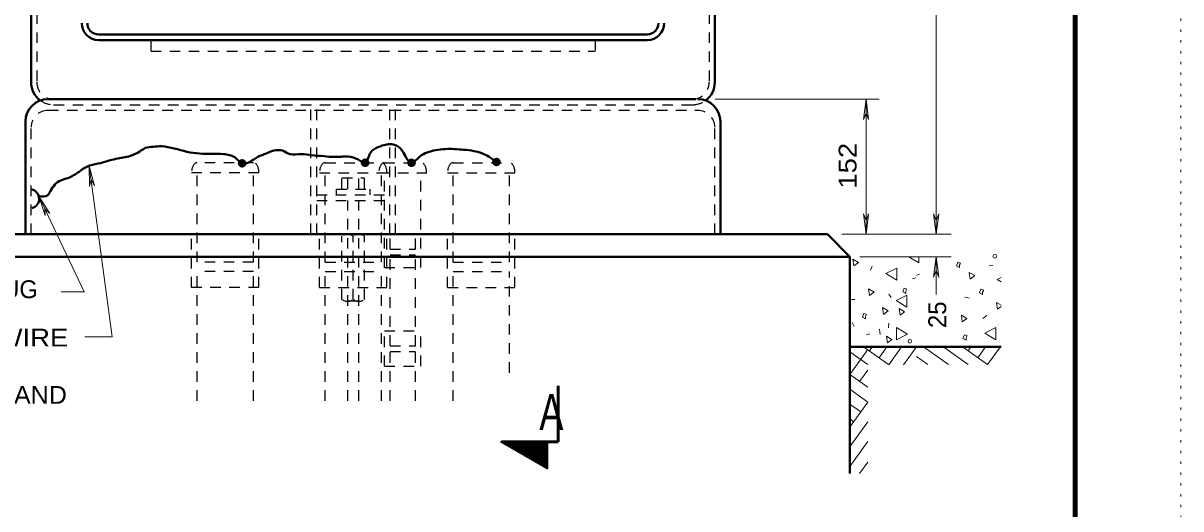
# Model space of a CAD drawing. Extents: x 312583 to 312854, y 144419 to 144597.
# Drawn here: x 312804.21 to 312853.5, y 144509.14 to 144529.81 of the extents above; entities that cross this region are included whole.
import ezdxf
from ezdxf.enums import TextEntityAlignment as Align

# ---------------------------------------------------------------- set-up
doc = ezdxf.new("R2010")
doc.units = 0
doc.header["$LTSCALE"] = 0.3
doc.linetypes.add('DOTTED', pattern=[1.5, 0.3, -1.2])
doc.linetypes.add('SHORT_DASHED', pattern=[2.7, 1.5, -1.2])
doc.layers.add('1', color=7, linetype='Continuous', lineweight=25)
doc.layers.add('2', color=7, linetype='Continuous', lineweight=13)

msp = doc.modelspace()

# ---------------------------------------------------------------- linework, layer by layer
at = {"layer": '1', "lineweight": 158}
msp.add_line((312849, 144423.1446), (312849, 144585.0846), dxfattribs=at)
at = {"layer": '1', "lineweight": 40}
for p, q in [((312804.5487, 144565.8673), (312804.5487, 144527.2963)), ((312833.659, 144565.8673), (312833.659, 144527.2963)), ((312807.4237, 144529.328), (312830.784, 144529.328)), ((312807.4237, 144529.0903), (312830.784, 144529.0903)), ((312805.2693, 144526.5756), (312832.8463, 144526.5756)), ((312804.311, 144520.8256), (312804.311, 144525.6173)), ((312833.8967, 144520.8256), (312833.8967, 144525.6173)), ((312838.4507, 144520.8256), (312839.409, 144519.8673)), ((312839.409, 144510.6366), (312839.409, 144519.8673)), ((312839.409, 144516.034), (312845.849, 144516.034))]:
    msp.add_line(p, q, dxfattribs=at)
at = {"layer": '1', "linetype": 'SHORT_DASHED'}
for p, q in [((312804.7863, 144565.8673), (312804.7863, 144527.2963)), ((312833.4213, 144565.8673), (312833.4213, 144527.2963)), ((312809.6393, 144529.0903), (312809.6393, 144528.615)), ((312828.5683, 144529.0903), (312828.5683, 144528.615)), ((312809.6393, 144528.615), (312828.5683, 144528.615)), ((312805.507, 144526.5756), (312832.7007, 144526.5756)), ((312805.507, 144526.338), (312832.7007, 144526.338)), ((312816.4627, 144520.8256), (312816.4627, 144526.338)), ((312816.708, 144520.8256), (312816.708, 144526.338)), ((312819.8207, 144520.8256), (312819.8207, 144526.338)), ((312820.0583, 144520.8256), (312820.0583, 144526.338)), ((312805.2693, 144526.1003), (312832.9383, 144526.1003)), ((312804.5487, 144520.8256), (312804.5487, 144525.3796)), ((312833.659, 144520.8256), (312833.659, 144525.3796)), ((312814.0093, 144523.8693), (312811.6173, 144523.8693)), ((312817.0683, 144523.8693), (312819.4603, 144523.8693)), ((312819.5907, 144523.8693), (312821.147, 144523.8693)), ((312822.5117, 144523.8693), (312824.9113, 144523.8693)), ((312814.247, 144523.4323), (312811.372, 144523.4323)), ((312811.6173, 144519.6373), (312811.6173, 144523.4323)), ((312814.0093, 144519.6373), (312814.0093, 144523.4323)), ((312816.823, 144523.4323), (312819.698, 144523.4323)), ((312817.0683, 144519.6373), (312817.0683, 144523.4323)), ((312819.353, 144523.4323), (312821.3923, 144523.4323)), ((312819.4603, 144519.6373), (312819.4603, 144523.4323)), ((312819.5907, 144519.4073), (312819.5907, 144523.4323)), ((312821.147, 144519.4073), (312821.147, 144523.4323)), ((312822.274, 144523.4323), (312825.149, 144523.4323)), ((312822.5117, 144519.6373), (312822.5117, 144523.4323)), ((312824.9113, 144519.6373), (312824.9113, 144523.4323)), ((312818.0267, 144522.7423), (312818.0267, 144523.2253)), ((312818.502, 144522.7423), (312818.502, 144523.2253)), ((312818.7397, 144522.7423), (312818.7397, 144523.2253)), ((312816.708, 144522.5046), (312819.8207, 144522.5046)), ((312817.5437, 144522.7423), (312818.985, 144522.7423)), ((312817.5437, 144522.5046), (312817.5437, 144522.7423)), ((312818.985, 144522.5046), (312818.985, 144522.7423)), ((312816.708, 144522.267), (312819.8207, 144522.267)), ((312818.0267, 144513.734), (312818.0267, 144522.267)), ((312818.502, 144513.734), (312818.502, 144522.267)), ((312811.372, 144518.5563), (312811.372, 144520.8256)), ((312814.247, 144518.5563), (312814.247, 144520.8256)), ((312816.823, 144518.5563), (312816.823, 144520.8256)), ((312819.698, 144518.5563), (312819.698, 144520.8256)), ((312819.8283, 144520.1893), (312819.8283, 144520.8256)), ((312820.9093, 144520.1893), (312820.9093, 144520.8256)), ((312822.274, 144518.5563), (312822.274, 144520.8256)), ((312825.149, 144518.5563), (312825.149, 144520.8256)), ((312817.7813, 144518.0503), (312817.7813, 144520.7413)), ((312818.2643, 144518.0503), (312818.2643, 144520.7413)), ((312818.7397, 144518.0503), (312818.7397, 144520.7413)), ((312819.8283, 144520.1893), (312820.9093, 144520.1893)), ((312819.8283, 144519.944), (312820.9093, 144519.944)), ((312819.8283, 144516.0723), (312819.8283, 144519.944)), ((312820.9093, 144516.0723), (312820.9093, 144519.944)), ((312814.0093, 144519.6373), (312811.6173, 144519.6373)), ((312817.0683, 144519.6373), (312819.4603, 144519.6373)), ((312819.5907, 144519.4073), (312821.147, 144519.4073)), ((312822.5117, 144519.6373), (312824.9113, 144519.6373)), ((312814.0093, 144519.2386), (312811.6173, 144519.2386)), ((312811.6173, 144513.734), (312811.6173, 144519.2386)), ((312814.0093, 144513.734), (312814.0093, 144519.2386)), ((312817.0683, 144519.2386), (312819.4603, 144519.2386)), ((312817.0683, 144513.734), (312817.0683, 144519.2386)), ((312819.4603, 144513.734), (312819.4603, 144519.2386)), ((312822.5117, 144519.2386), (312824.9113, 144519.2386)), ((312822.5117, 144513.734), (312822.5117, 144519.2386)), ((312824.9113, 144514.93), (312824.9113, 144519.2386)), ((312814.247, 144518.5563), (312811.372, 144518.5563)), ((312816.823, 144518.5563), (312819.698, 144518.5563)), ((312822.274, 144518.5563), (312825.149, 144518.5563)), ((312818.502, 144517.9736), (312818.0267, 144517.9736)), ((312819.5907, 144515.206), (312819.5907, 144516.7163)), ((312819.5907, 144516.7163), (312821.147, 144516.7163)), ((312821.147, 144515.206), (312821.147, 144516.7163)), ((312819.8283, 144516.0723), (312820.9093, 144516.0723)), ((312819.8283, 144515.827), (312820.9093, 144515.827)), ((312819.8283, 144513.734), (312819.8283, 144515.827)), ((312820.9093, 144513.734), (312820.9093, 144515.827)), ((312819.5907, 144515.206), (312821.147, 144515.206))]:
    msp.add_line(p, q, dxfattribs=at)
at = {"layer": '1', "lineweight": 53}
for p in [(312826.9813, 144514.378), (312826.506, 144511.986)]:
    msp.add_line(p, (312826.9813, 144511.986), dxfattribs=at)
at = {"layer": '1', "lineweight": 35}
for p, q in [((312824.6047, 144511.986), (312824.6047, 144511.9706)), ((312824.6353, 144511.986), (312824.6277, 144511.963)), ((312824.666, 144511.986), (312824.643, 144511.9476)), ((312824.689, 144511.986), (312824.666, 144511.94)), ((312824.7197, 144511.986), (312824.689, 144511.9246)), ((312824.7427, 144511.986), (312824.7043, 144511.917)), ((312824.7733, 144511.986), (312824.7273, 144511.9016)), ((312824.804, 144511.986), (312824.7503, 144511.894)), ((312824.8347, 144511.986), (312824.7657, 144511.8786)), ((312824.8577, 144511.986), (312824.7887, 144511.871)), ((312824.8807, 144511.986), (312824.8117, 144511.8556)), ((312824.9113, 144511.986), (312824.8347, 144511.848)), ((312824.9343, 144511.986), (312824.85, 144511.8326)), ((312824.965, 144511.986), (312824.873, 144511.8173)), ((312824.9957, 144511.986), (312824.896, 144511.8096)), ((312825.0263, 144511.986), (312824.9113, 144511.7943)), ((312825.0493, 144511.986), (312824.9343, 144511.779)), ((312825.08, 144511.986), (312824.9573, 144511.7713)), ((312825.103, 144511.986), (312824.9727, 144511.756)), ((312825.1337, 144511.986), (312824.9957, 144511.7483)), ((312825.1643, 144511.986), (312825.0187, 144511.733)), ((312825.1873, 144511.986), (312825.034, 144511.7253)), ((312825.218, 144511.986), (312825.0647, 144511.71)), ((312825.241, 144511.986), (312825.08, 144511.7023)), ((312825.2717, 144511.986), (312825.103, 144511.687)), ((312825.3023, 144511.986), (312825.126, 144511.6793)), ((312825.3253, 144511.986), (312825.1413, 144511.664)), ((312825.356, 144511.986), (312825.1643, 144511.6563)), ((312825.379, 144511.986), (312825.1873, 144511.641)), ((312825.4097, 144511.986), (312825.2027, 144511.6256)), ((312825.4327, 144511.986), (312825.2257, 144511.618)), ((312825.4633, 144511.986), (312825.2487, 144511.6026)), ((312825.494, 144511.986), (312825.264, 144511.5873)), ((312825.5247, 144511.986), (312825.287, 144511.5796)), ((312825.5477, 144511.986), (312825.31, 144511.5643)), ((312825.5707, 144511.986), (312825.333, 144511.5566)), ((312825.6013, 144511.986), (312825.3483, 144511.5413)), ((312825.632, 144511.986), (312825.3713, 144511.5336)), ((312825.655, 144511.986), (312825.3943, 144511.5183)), ((312825.6857, 144511.986), (312825.4097, 144511.5106)), ((312825.7163, 144511.986), (312825.4327, 144511.4953)), ((312825.7393, 144511.986), (312825.4557, 144511.4876)), ((312825.77, 144511.986), (312825.471, 144511.4723)), ((312825.8007, 144511.986), (312825.494, 144511.4646)), ((312825.8237, 144511.986), (312825.517, 144511.4493)), ((312825.8543, 144511.9783), (312825.5323, 144511.434)), ((312825.8773, 144511.986), (312825.563, 144511.4263)), ((312825.908, 144511.986), (312825.5783, 144511.411)), ((312825.931, 144511.986), (312825.6013, 144511.4033)), ((312825.9617, 144511.986), (312825.6243, 144511.388)), ((312825.9923, 144511.986), (312825.6397, 144511.3803)), ((312826.023, 144511.986), (312825.6627, 144511.365)), ((312826.046, 144511.986), (312825.6857, 144511.3573)), ((312826.069, 144511.986), (312825.701, 144511.342)), ((312826.0997, 144511.9783), (312825.724, 144511.3343)), ((312826.1303, 144511.986), (312825.747, 144511.319)), ((312826.1533, 144511.986), (312825.7623, 144511.3113)), ((312826.184, 144511.986), (312825.7853, 144511.296)), ((312826.2147, 144511.986), (312825.8083, 144511.2806)), ((312826.2377, 144511.986), (312825.8313, 144511.273)), ((312826.2683, 144511.986), (312825.8467, 144511.2576)), ((312826.299, 144511.986), (312825.8697, 144511.2423)), ((312826.322, 144511.9783), (312825.8927, 144511.2346)), ((312826.3527, 144511.9783), (312825.908, 144511.2193)), ((312826.3757, 144511.986), (312825.931, 144511.2116)), ((312826.4063, 144511.986), (312825.954, 144511.1963)), ((312826.4293, 144511.986), (312825.9693, 144511.1886)), ((312826.46, 144511.986), (312825.9923, 144511.1733)), ((312826.4907, 144511.986), (312826.0153, 144511.1656)), ((312826.506, 144511.963), (312826.0307, 144511.1503)), ((312826.506, 144511.9093), (312826.0613, 144511.1426)), ((312826.506, 144511.871), (312826.0767, 144511.1273)), ((312826.506, 144511.8173), (312826.0997, 144511.1196)), ((312826.506, 144511.7713), (312826.1227, 144511.1043)), ((312826.506, 144511.7253), (312826.138, 144511.089)), ((312826.506, 144511.6793), (312826.161, 144511.0813)), ((312826.506, 144511.6256), (312826.184, 144511.066)), ((312826.506, 144511.5796), (312826.1993, 144511.0506)), ((312826.506, 144511.5336), (312826.2223, 144511.043)), ((312826.506, 144511.48), (312826.2377, 144511.0276)), ((312826.506, 144511.434), (312826.2607, 144511.02)), ((312826.506, 144511.388), (312826.2837, 144511.0046)), ((312826.506, 144511.3343), (312826.299, 144510.997)), ((312826.506, 144511.2883), (312826.3297, 144510.9816)), ((312826.506, 144511.2423), (312826.345, 144510.974)), ((312826.506, 144511.1963), (312826.368, 144510.9586)), ((312826.506, 144511.1426), (312826.391, 144510.951)), ((312826.506, 144511.1043), (312826.4063, 144510.9356)), ((312826.506, 144511.0506), (312826.4293, 144510.928)), ((312826.506, 144511.0046), (312826.4523, 144510.9126)), ((312826.506, 144510.951), (312826.4677, 144510.8973)), ((312826.506, 144510.905), (312826.4907, 144510.8896))]:
    msp.add_line(p, q, dxfattribs=at)
at = {"layer": '1', "linetype": 'DOTTED', "lineweight": 13}
msp.add_lwpolyline([(312601.2, 144418.5846), (312853.5, 144418.5846), (312853.5, 144596.7846)], dxfattribs=at)
at = {"layer": '1', "linetype": 'SHORT_DASHED'}
msp.add_lwpolyline([(312817.7813, 144522.7423), (312817.7813, 144523.2253), (312818.7397, 144523.2253)], dxfattribs=at)
at = {"layer": '1', "lineweight": 40}
for points in [[(312750.646, 144520.8256), (312769.3932, 144520.8256), (312838.4507, 144520.8256)], [(312749.6877, 144519.8673), (312769.3932, 144519.8673), (312839.409, 144519.8673)]]:
    msp.add_lwpolyline(points, dxfattribs=at)
at = {"layer": '1', "lineweight": 53}
msp.add_lwpolyline([(312826.506, 144511.986), (312826.506, 144510.8743), (312824.5893, 144511.986)], close=True, dxfattribs=at)
at = {"layer": '1', "lineweight": 40}
for centre, radius in [((312813.533, 144523.8434), 0.1358), ((312813.533, 144523.8434), 0.1174), ((312813.533, 144523.8434), 0.1057), ((312813.533, 144523.8434), 0.0822), ((312813.533, 144523.8434), 0.0575), ((312813.533, 144523.8434), 0.0403), ((312813.533, 144523.8434), 0.0282), ((312813.533, 144523.8434), 0.0197), ((312813.533, 144523.8434), 0.0138), ((312818.7684, 144523.8674), 0.1358), ((312818.7684, 144523.8674), 0.1174), ((312818.7684, 144523.8674), 0.1057), ((312818.7684, 144523.8674), 0.0822), ((312818.7684, 144523.8674), 0.0575), ((312818.7684, 144523.8674), 0.0403), ((312818.7684, 144523.8674), 0.0282), ((312818.7684, 144523.8674), 0.0197), ((312818.7684, 144523.8674), 0.0138), ((312820.7464, 144523.8674), 0.1358), ((312820.7464, 144523.8674), 0.1174), ((312820.7464, 144523.8674), 0.1057), ((312820.7464, 144523.8674), 0.0822), ((312820.7464, 144523.8674), 0.0575), ((312820.7464, 144523.8674), 0.0403), ((312820.7464, 144523.8674), 0.0282), ((312820.7464, 144523.8674), 0.0197), ((312820.7464, 144523.8674), 0.0138), ((312824.3603, 144523.9), 0.1358), ((312824.3603, 144523.9), 0.1174), ((312824.3603, 144523.9), 0.1057), ((312824.3603, 144523.9), 0.0822), ((312824.3603, 144523.9), 0.0575), ((312824.3603, 144523.9), 0.0403), ((312824.3603, 144523.9), 0.0282), ((312824.3603, 144523.9), 0.0197), ((312824.3603, 144523.9), 0.0138)]:
    msp.add_circle(centre, radius, dxfattribs=at)
for centre, radius, start, end in [((312807.4217, 144529.81), 0.7188, 180, 270), ((312807.4217, 144529.81), 0.4792, 180, 270), ((312830.7821, 144529.81), 0.7188, 270, 0), ((312830.7821, 144529.81), 0.4792, 270, 0), ((312805.5051, 144527.2944), 0.9583, 180, 233.98433), ((312832.6987, 144527.2944), 0.9583, 306.01567, 0), ((312805.2655, 144525.6173), 0.9583, 90, 180), ((312832.9383, 144525.6173), 0.9583, 0, 90), ((312804.4814, 144522.3336), 0.4076, 285.15764, 77.61644)]:
    msp.add_arc(centre, radius, start, end, dxfattribs=at)
at = {"layer": '1', "linetype": 'SHORT_DASHED'}
for centre, radius, start, end in [((312805.5051, 144527.2944), 0.7188, 180, 270), ((312832.6987, 144527.2944), 0.7188, 270, 0), ((312805.5051, 144527.2944), 0.9583, 233.98433, 270), ((312832.6987, 144527.2944), 0.9583, 270, 306.01567), ((312805.2655, 144525.3777), 0.7188, 90, 180), ((312832.9383, 144525.3777), 0.7188, 0, 90), ((312818.0228, 144520.4379), 0.3858, 51.61151, 128.38849), ((312818.502, 144520.4045), 0.4125, 54.49327, 125.50673), ((312818.0228, 144518.3823), 0.4125, 234.49327, 305.50673), ((312818.502, 144518.3823), 0.4125, 234.49327, 305.50673)]:
    msp.add_arc(centre, radius, start, end, dxfattribs=at)
for centre, major_axis, start_param, end_param in [((312811.6145, 144523.4352), (0, -0.4351), 3.1415927, 4.712389), ((312814.0103, 144523.4352), (0, 0.4351), 4.712389, 6.2831853), ((312817.0645, 144523.4352), (0, -0.4351), 3.1415927, 4.712389), ((312819.5916, 144523.4352), (0, -0.4351), 3.1415927, 4.712389), ((312819.4603, 144523.4352), (0, 0.4351), 4.712389, 6.2831853), ((312821.1489, 144523.4352), (0, 0.4351), 4.712389, 6.2831853), ((312822.5145, 144523.4352), (0, -0.4351), 3.1415927, 4.712389), ((312824.9104, 144523.4352), (0, 0.4351), 4.712389, 6.2831853)]:
    msp.add_ellipse(centre, major_axis=major_axis, ratio=0.550661, start_param=start_param, end_param=end_param, dxfattribs=at)
at = {"layer": '1', "lineweight": 40}
for points in [[(312809.4017, 144524.498), (312808.7807, 144524.1606), (312808.1597, 144524.0303), (312807.4007, 144523.831), (312806.9253, 144523.7006), (312806.588, 144523.486), (312806.1127, 144523.2176), (312805.806, 144523.118), (312805.3767, 144522.6733), (312805.254, 144522.4816), (312804.8783, 144522.4433)], [(312824.3593, 144523.9), (312824.0527, 144524.1146), (312823.401, 144524.3676), (312822.964, 144524.4213), (312822.1743, 144524.452), (312821.4077, 144524.3063), (312821.101, 144524.13), (312820.7483, 144523.8693), (312820.4033, 144524.291), (312820.2577, 144524.4826), (312820.02, 144524.6283), (312819.4987, 144524.5976), (312819.1383, 144524.4366), (312818.9927, 144524.291), (312818.7703, 144523.8693), (312818.479, 144523.9996), (312818.042, 144524.13), (312817.444, 144524.1146), (312817.0223, 144524.1453), (312816.4857, 144524.1913), (312816.0487, 144524.2373), (312815.5733, 144524.2373), (312815.2513, 144524.383), (312814.8757, 144524.383), (312814.5537, 144524.2603), (312814.201, 144524.1146), (312813.534, 144523.8463), (312813.2427, 144524.0763), (312812.7367, 144524.2373), (312811.717, 144524.2603), (312811.1803, 144524.337), (312810.0993, 144524.567), (312809.4017, 144524.498)]]:
    msp.add_spline(points, degree=3, dxfattribs=at)
at = {"layer": '2'}
for p, q in [((312843.0813, 144520.8256), (312843.0813, 144566.8256)), ((312833.6743, 144526.5756), (312840.6587, 144526.5756)), ((312840.099, 144526.5756), (312839.9917, 144525.7093)), ((312840.099, 144520.8256), (312840.099, 144526.5756)), ((312840.099, 144526.5756), (312840.2063, 144525.7093)), ((312839.9917, 144525.7093), (312840.099, 144525.9853)), ((312840.2063, 144525.7093), (312840.099, 144525.9853)), ((312807.9987, 144516.4633), (312807.025, 144523.7313)), ((312807.025, 144523.7313), (312807.0327, 144522.8573)), ((312807.025, 144523.7313), (312807.2473, 144522.888)), ((312807.0327, 144522.8573), (312807.1017, 144523.1486)), ((312807.2473, 144522.888), (312807.1017, 144523.1486)), ((312806.8027, 144518.3723), (312804.8783, 144522.4433)), ((312804.8783, 144522.4433), (312805.1467, 144521.6153)), ((312804.8783, 144522.4433), (312805.346, 144521.7073)), ((312805.1467, 144521.6153), (312805.1313, 144521.9066)), ((312805.346, 144521.7073), (312805.1313, 144521.9066)), ((312839.9917, 144521.692), (312840.099, 144521.416)), ((312840.099, 144520.8256), (312839.9917, 144521.692)), ((312840.2063, 144521.692), (312840.099, 144521.416)), ((312840.099, 144520.8256), (312840.2063, 144521.692)), ((312842.974, 144521.692), (312843.0813, 144521.416)), ((312843.0813, 144520.8256), (312842.974, 144521.692)), ((312843.1887, 144521.692), (312843.0813, 144521.416)), ((312843.0813, 144520.8256), (312843.1887, 144521.692)), ((312839.064, 144520.8256), (312843.7253, 144520.8256)), ((312839.8383, 144519.8673), (312843.7253, 144519.8673)), ((312841.916, 144519.8673), (312842.3453, 144519.6066)), ((312842.3453, 144519.6066), (312842.3453, 144519.8673)), ((312843.0813, 144519.8673), (312842.974, 144519.001)), ((312843.0813, 144518.2618), (312843.0813, 144519.8673)), ((312843.0813, 144519.8673), (312843.1887, 144519.001)), ((312840.3597, 144519.461), (312840.283, 144519.2923)), ((312845.343, 144519.484), (312845.4887, 144519.4916)), ((312842.0693, 144518.932), (312842.2227, 144518.9626)), ((312842.238, 144519.0623), (312842.3683, 144519.1313)), ((312842.974, 144519.001), (312843.0813, 144519.277)), ((312843.1887, 144519.001), (312843.0813, 144519.277)), ((312805.829, 144518.3723), (312806.8027, 144518.3723)), ((312839.4703, 144518.0426), (312839.616, 144518.0503)), ((312841.065, 144518.2726), (312841.1723, 144518.1346)), ((312844.308, 144518.1423), (312844.4843, 144518.104)), ((312845.2433, 144517.368), (312845.067, 144517.2376)), ((312845.6957, 144517.6363), (312845.849, 144517.7513)), ((312839.5087, 144517.069), (312839.593, 144516.9003)), ((312841.0479, 144516.8466), (312841.0709, 144517.0383)), ((312806.8333, 144516.4633), (312807.9987, 144516.4633)), ((312840.1143, 144516.54), (312840.26, 144516.5783)), ((312840.674, 144516.7776), (312840.697, 144516.563)), ((312840.168, 144515.919), (312839.409, 144514.8533)), ((312839.7387, 144516.034), (312839.7387, 144516.0416)), ((312841.0497, 144515.275), (312839.984, 144516.034)), ((312840.352, 144516.0263), (312840.237, 144515.8576)), ((312840.9807, 144516.0263), (312840.651, 144515.5586)), ((312841.6093, 144516.0263), (312841.065, 144515.2596)), ((312842.238, 144516.0263), (312841.6937, 144515.2596)), ((312843.6027, 144515.275), (312842.537, 144516.034)), ((312844.446, 144515.275), (312843.4033, 144516.011)), ((312845.274, 144515.275), (312844.193, 144516.0493)), ((312844.561, 144516.034), (312844.446, 144515.8653)), ((312845.1897, 144516.034), (312844.86, 144515.5663)), ((312845.8183, 144516.034), (312845.274, 144515.275)), ((312840.168, 144515.275), (312839.409, 144515.8193)), ((312842.721, 144515.275), (312842.238, 144515.62)), ((312840.168, 144515.0373), (312839.823, 144514.5543)), ((312839.409, 144514.8533), (312840.168, 144514.309)), ((312839.409, 144514.2246), (312840.168, 144513.6803)), ((312840.168, 144513.6803), (312839.3937, 144512.5916)), ((312839.409, 144513.596), (312839.869, 144513.2663)), ((312839.409, 144512.9673), (312839.5777, 144512.8446)), ((312840.168, 144512.8446), (312839.4243, 144511.8096)), ((312840.168, 144512.0013), (312839.409, 144510.9356)), ((312840.168, 144511.1273), (312839.823, 144510.6366))]:
    msp.add_line(p, q, dxfattribs=at)
for points in [[(312839.5777, 144519.4763), (312839.7693, 144519.622), (312839.5393, 144519.76)], [(312841.4023, 144518.8706), (312841.4023, 144519.3843), (312840.9347, 144519.1543)], [(312844.078, 144519.5223), (312844.124, 144519.599), (312844.009, 144519.6373), (312843.9477, 144519.484), (312844.078, 144519.415)], [(312844.5303, 144518.909), (312844.7297, 144519.0623), (312844.492, 144519.2003)], [(312840.2447, 144518.2113), (312840.4363, 144518.357), (312840.2063, 144518.495)], [(312841.7933, 144518.403), (312841.8393, 144518.4873), (312841.7243, 144518.5256), (312841.663, 144518.3723), (312841.7933, 144518.3033)], [(312845.0593, 144518.3646), (312845.1053, 144518.4413), (312844.9903, 144518.4796), (312844.929, 144518.3263), (312845.0593, 144518.2573)], [(312841.8369, 144517.7176), (312841.8369, 144518.2313), (312841.3769, 144518.0013)], [(312840.076, 144517.3296), (312840.122, 144517.414), (312840.007, 144517.4446), (312839.9457, 144517.299), (312840.076, 144517.2223)], [(312840.8427, 144517.414), (312841.0343, 144517.5673), (312840.7967, 144517.7053)], [(312841.548, 144517.3756), (312841.7397, 144517.5213), (312841.502, 144517.6593)], [(312844.193, 144517.092), (312844.3847, 144517.2376), (312844.1547, 144517.3756)], [(312841.0071, 144516.2026), (312841.1988, 144516.3483), (312840.9688, 144516.4863)], [(312841.387, 144516.8543), (312841.387, 144516.333), (312841.8547, 144516.5706)], [(312844.3549, 144516.4236), (312844.4009, 144516.5079), (312844.2859, 144516.5386), (312844.2246, 144516.3929), (312844.3549, 144516.3162)], [(312845.619, 144516.333), (312845.619, 144516.8543), (312845.1513, 144516.6166)]]:
    msp.add_lwpolyline(points, close=True, dxfattribs=at)
for points in [[(312845.849, 144518.9856), (312845.6727, 144518.9013), (312845.849, 144518.794)], [(312845.849, 144517.805), (312845.6573, 144517.92), (312845.6957, 144517.6363)]]:
    msp.add_lwpolyline(points, dxfattribs=at)
for centre in [(312845.5789, 144519.8884), (312841.9616, 144516.2711)]:
    msp.add_circle(centre, 0.0784, dxfattribs=at)

# ---------------------------------------------------------------- texts
at = {"layer": '1', "width": 0.75}
msp.add_text('A', height=1.533, dxfattribs=at).set_placement((312826.6977, 144512.492), align=Align.CENTER)
at = {"layer": '2', "width": 1.15}
msp.add_text('152 ', height=0.76, rotation=90, dxfattribs=at).set_placement((312839.6913, 144522.7654))
at = {"layer": '2'}
msp.add_text('GROUND LUG', height=0.76, dxfattribs=at).set_placement((312797.9482, 144518.103))
msp.add_text('25', height=0.76, rotation=90, dxfattribs=at).set_placement((312843.5085, 144516.8316))
for s, width, p in [('#8 BARE WIRE', 1.15, (312797.9483, 144516.0467)), ('CONDUITS AND', 1.05, (312797.9483, 144513.6067))]:
    msp.add_text(s, height=0.76, dxfattribs=dict(at, width=width)).set_placement(p)

doc.saveas('drawing.dxf')
